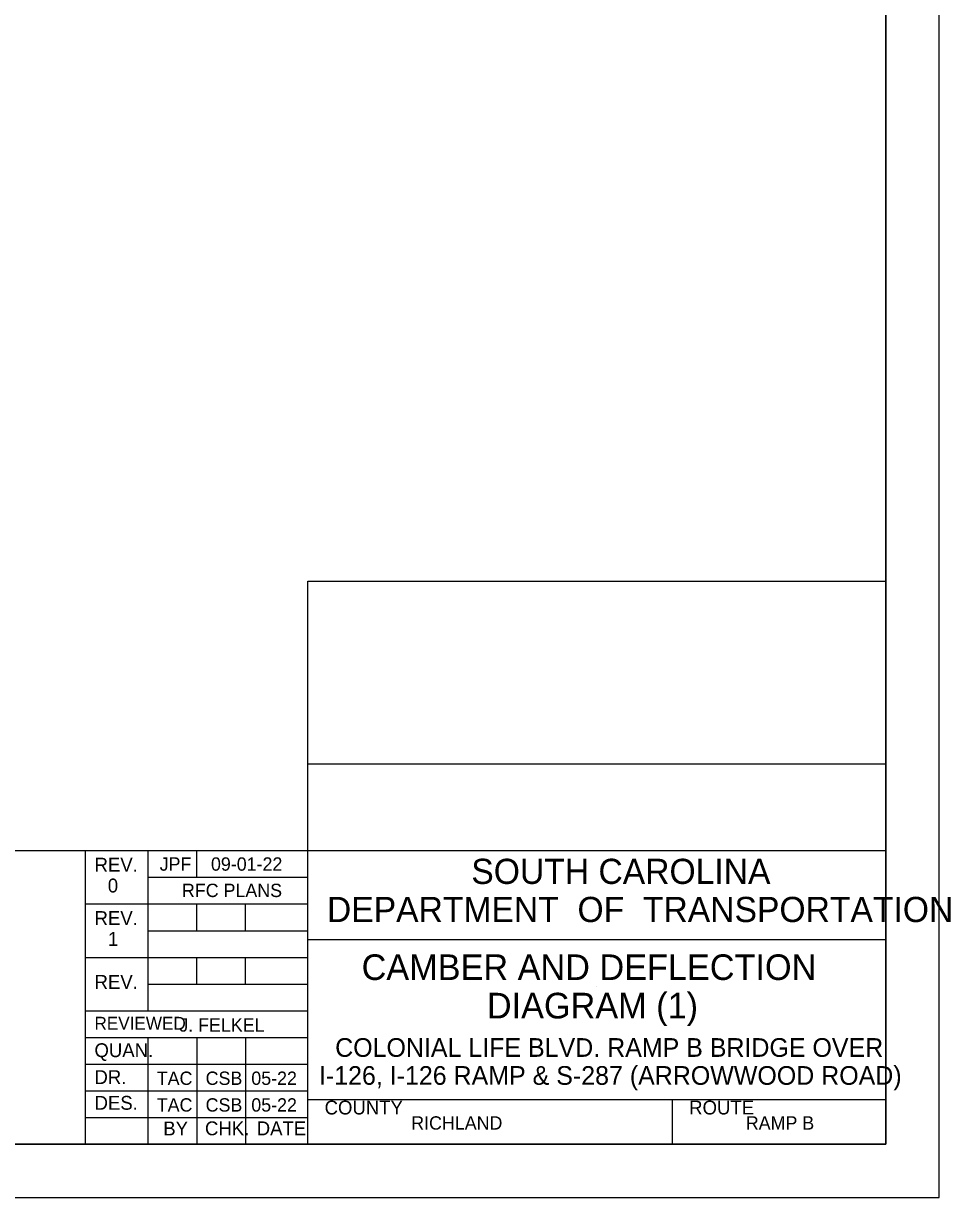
# Model space of a CAD drawing. Extents: x -125.5 to -89.4, y -5.1 to 16.9.
# Drawn here: x -98.12 to -89.43, y -5.07 to 5.93 of the extents above; entities that cross this region are included whole.
import ezdxf

# ---------------------------------------------------------------- set-up
doc = ezdxf.new("R2010")
doc.units = 0
for name, color, linetype in [('BR_BORDER LINES', 7, 'Continuous'), ('BR_TABLE LINES', 7, 'Continuous'), ('BR_TEXT', 7, 'Continuous'), ('Level 31', 7, 'Continuous')]:
    doc.layers.add(name, color=color, linetype=linetype)

msp = doc.modelspace()

# ---------------------------------------------------------------- linework, layer by layer
at = {"layer": 'BR_BORDER LINES'}
for p, q in [((-90.033, -4.566), (-90.033, 16.434)), ((-95.45, -4.566), (-95.45, 0.71)), ((-95.45, 0.71), (-90.033, 0.71)), ((-95.45, -1.004), (-90.033, -1.004)), ((-102.899, -1.816), (-97.534, -1.816)), ((-97.534, -4.566), (-97.534, -1.816)), ((-97.534, -1.816), (-90.033, -1.816)), ((-96.95, -1.816), (-96.95, -3.316)), ((-96.492, -2.066), (-96.492, -1.816)), ((-96.95, -2.066), (-95.45, -2.066)), ((-97.534, -2.316), (-95.45, -2.316)), ((-96.492, -2.566), (-96.492, -2.316)), ((-96.034, -2.566), (-96.034, -2.316)), ((-96.95, -2.566), (-95.45, -2.566)), ((-95.45, -2.649), (-95.45, -2.649)), ((-95.45, -2.649), (-90.033, -2.649)), ((-97.534, -2.816), (-95.45, -2.816)), ((-96.492, -3.066), (-96.492, -2.816)), ((-96.034, -3.066), (-96.034, -2.816)), ((-96.95, -3.066), (-95.45, -3.066)), ((-97.534, -3.316), (-95.45, -3.316)), ((-97.534, -3.566), (-95.45, -3.566)), ((-96.95, -3.566), (-96.95, -4.566)), ((-96.492, -3.566), (-96.492, -4.566)), ((-96.034, -3.566), (-96.034, -4.566)), ((-97.534, -3.816), (-95.45, -3.816)), ((-97.534, -4.066), (-95.45, -4.066)), ((-95.45, -4.149), (-90.033, -4.149)), ((-95.353, -4.149), (-90.033, -4.149)), ((-92.033, -4.566), (-92.033, -4.149)), ((-97.534, -4.316), (-95.45, -4.316)), ((-123.699, -4.566), (-90.033, -4.566))]:
    msp.add_line(p, q, dxfattribs=at)
at = {"layer": 'BR_TABLE LINES'}
msp.add_lwpolyline([(-123.699, 16.434), (-90.033, 16.434), (-90.033, -4.566), (-123.699, -4.566)], close=True, dxfattribs=at)
at = {"layer": 'Level 31'}
msp.add_line((-92.742, -3.09), (-92.742, -3.09), dxfattribs=at)
msp.add_lwpolyline([(-125.533, -5.066), (-89.533, -5.066), (-89.533, 16.934), (-125.533, 16.934)], close=True, dxfattribs=at)

# ---------------------------------------------------------------- texts
at = {"layer": 'BR_TEXT'}
for s, height, p in [('REV.', 0.13, (-97.449, -2.013)), ('JPF', 0.125, (-96.839, -2.004)), ('09-01-22', 0.125, (-96.358, -2.004)), ('SOUTH CAROLINA', 0.23587, (-93.918, -2.128)), ('0', 0.13, (-97.325, -2.208)), ('RFC PLANS', 0.125, (-96.63, -2.251)), ('DEPARTMENT  OF  TRANSPORTATION', 0.23587, (-95.271, -2.485)), ('REV.', 0.13, (-97.449, -2.513)), ('1', 0.13, (-97.323, -2.708)), ('CAMBER AND DEFLECTION', 0.24, (-94.946, -3.028)), ('REV.', 0.13, (-97.449, -3.111)), ('DIAGRAM (1)', 0.24, (-93.772, -3.388)), ('REVIEWED', 0.12, (-97.45, -3.493)), ('J. FELKEL', 0.125, (-96.655, -3.512)), ('QUAN.', 0.13, (-97.45, -3.751)), ('COLONIAL LIFE BLVD. RAMP B BRIDGE OVER', 0.175, (-95.194, -3.748)), ('I-126, I-126 RAMP & S-287 (ARROWWOOD ROAD) ', 0.175, (-95.346, -4.01)), ('DR.', 0.13, (-97.45, -4.003)), ('TAC', 0.125, (-96.866, -4.011)), ('CSB', 0.125, (-96.408, -4.011)), ('05-22', 0.125, (-95.98, -4.011)), ('DES.', 0.13, (-97.449, -4.244)), ('TAC', 0.125, (-96.866, -4.261)), ('CSB', 0.125, (-96.408, -4.261)), ('05-22', 0.125, (-95.98, -4.261)), ('COUNTY', 0.13, (-95.293, -4.288)), ('ROUTE', 0.13, (-91.876, -4.288)), ('BY', 0.13, (-96.805, -4.484)), ('CHK.', 0.13, (-96.414, -4.483)), ('DATE', 0.13, (-95.929, -4.483)), ('RICHLAND', 0.125, (-94.481, -4.43)), ('RAMP B', 0.125, (-91.345, -4.43))]:
    msp.add_text(s, height=height, dxfattribs=at).set_placement(p)

doc.saveas('drawing.dxf')
